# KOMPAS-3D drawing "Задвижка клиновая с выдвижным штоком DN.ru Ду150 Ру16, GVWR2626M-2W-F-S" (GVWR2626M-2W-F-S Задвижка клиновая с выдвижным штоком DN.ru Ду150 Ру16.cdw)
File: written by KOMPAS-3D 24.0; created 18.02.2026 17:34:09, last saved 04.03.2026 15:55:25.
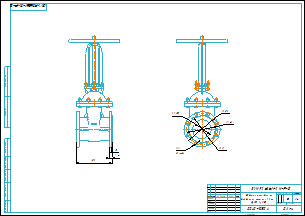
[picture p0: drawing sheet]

Document properties: art: D040-10504; Автор: R2D2; Форматы листов документа: A2; Полное имя файла: GVWR2626M-2W-F-S Задвижка клиновая с выдвижным штоком DN.ru Ду150 Ру16.m3d; Масса: 67; Наименование: Задвижка клиновая с выдвижным штоком DN.ru Ду150 Ру16; Количество листов документа: 1; Примечание: D040-10504

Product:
- Part/product: Задвижка клиновая с выдвижным штоком DN.ru Ду150 Ру16  | designation GVWR2626M-2W-F-S
    Масса: 67
    Раздел спецификации: Прочие изделия
    Примечание: D040-10504
    additional columns: D040-10504

Referenced files in E:\Работа\Зайцев\Для компаса\: чертеж DN.ru А3.cdt
Referenced files in E:\Работа\Зайцев\GVWR2626M-2W-F-S Задвижка клиновая с выдвижным штоком DN.ru Ду50-300 Ру16\DN150\: GVWR2626M-2W-F-S Задвижка клиновая с выдвижным штоком DN.ru Ду150 Ру16.m3d
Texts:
  чертеж DN.ru А3.cdt
  Задвижка клиновая с
  выдвижным штоком DN.ru
  Ду150 Ру16
  GVWR2626M-2W-F-S
  Задвижка клиновая с выдвижным штоком DN.ru Ду150 Ру16
  GVWR2626M-2W-F-S Задвижка клиновая с выдвижным штоком DN.ru Ду150 Ру16
Dimensions and other numbers on the sheet: 1:4; 0; 1; 2; 67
